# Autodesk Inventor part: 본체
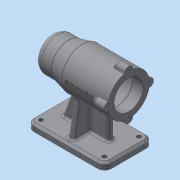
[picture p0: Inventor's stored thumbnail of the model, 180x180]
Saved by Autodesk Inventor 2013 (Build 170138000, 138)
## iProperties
Created: 2019-07
Part Number: 본체
Material: 일반
Document SubType Name: Modeling
Designer: dgall
Density: 1 g/cm^3
Author: dgall
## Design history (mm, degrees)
sketch "스케치1"
  geometry: L1 (0, 0)-(112, 0); L2 (112, 0)-(112, 70); L3 (112, 70)-(0, 70); L4 (0, 70)-(0, 0)
  constraints: 8 end point, 2 parallel, 1 horizontal, 1 perpendicular
  dimensions: "d5" = 70 distance of L1.end L2.end; "d6" = 112 distance of L2.end L3.end
extrude "돌출1" new body sketch "스케치1" distance "d7" = 10; taper "d8" = 0 deg
fillet "모깎기1" dims "d9" = 10
chamfer "모따기1" distance "d10" = 3; stored, may be unused: second distance "d11" = 2, angle "d12" = 45 deg
hole "구멍1" diameter "d15" = 6; stored, may be unused: countersink angle "d19" = 90 deg, drill point angle "d21" = 118 deg; dims "d13" = 10, "d14" = 10, "d16" = 6, "d17" = 4, "d18" = 2, "d20" = 27.5
hole "구멍2" diameter "d24" = 6; stored, may be unused: countersink angle "d28" = 90 deg, drill point angle "d30" = 118 deg; dims "d22" = 10, "d23" = 10, "d25" = 6, "d26" = 4, "d27" = 2, "d29" = 27.5
hole "구멍3" diameter "d33" = 6; stored, may be unused: countersink angle "d37" = 90 deg, drill point angle "d39" = 118 deg; dims "d31" = 10, "d32" = 10, "d34" = 6, "d35" = 4, "d36" = 2, "d38" = 27.5
hole "구멍4" diameter "d42" = 6; stored, may be unused: countersink angle "d46" = 90 deg, drill point angle "d48" = 118 deg; dims "d40" = 10, "d41" = 10, "d43" = 6, "d44" = 4, "d45" = 2, "d47" = 27.5
node "작업 평면2"
sketch "스케치2"
  geometry: L1 (0, 0)-(-112, 0); L2 (-56, 0)-(-56, 80); L3 (-56, 80)-(-112, 80); L4 (-56, 80)-(0, 80); L5 (-112, 80)-(-112, 101); L6 (-112, 101)-(-97, 101); L7 (-97, 101)-(-97, 101); L8 (-94, 104)-(-46, 104); L9 (-43, 101)-(-43, 101); L10 (-43, 101)-(-31.3, 101); L11 (-31, 100.7)-(-31, 97.5); L12 (-31, 97.5)-(-13.3, 97.5); L13 (-13, 97.2)-(-13, 96); L14 (-13, 96)-(-9.3, 96); L15 (-9, 95.7)-(-9, 90.5); L16 (-9, 90.5)-(-9, 90.5); L17 (-6, 87.5)-(-6, 80); L18 (0, 80)-(0, 95); L19 (-10, 105)-(-25, 105); L20 (-25, 105)-(-45, 110); L21 (-45, 110)-(-112, 110); L22 (-112, 110)-(-112, 101); A1 r 0.3 centre (-9.3, 95.7) between (-9, 95.7) and (-9.3, 96); A2 r 0.3 centre (-13.3, 97.2) between (-13, 97.2) and (-13.3, 97.5); A3 r 0.3 centre (-31.3, 100.7) between (-31, 100.7) and (-31.3, 101); A4 r 3 centre (-46, 101) between (-43, 101) and (-46, 104); A5 r 3 centre (-94, 101) between (-94, 104) and (-97, 101); A6 r 3 centre (-9, 87.5) between (-6, 87.5) and (-9, 90.5); A7 r 10 centre (-10, 95) between (0, 95) and (-10, 105); 7 further points
  constraints: 44 end point, 17 perpendicular, 15 point on line, 14 point on circle, 14 tangent, 7 centre point, 3 equal radius, 2 parallel, 1 collinear, 1 horizontal, 1 midpoint
  dimensions: "d50" = 112 distance of L1.start L1.end; "d54" = 80 distance of L2.start L2.end; "d55" = 21 distance of L3.end L5.end; "d57" = 48 diameter of point (-97, 104) L3; "d58" = 54 distance of point (-97, 104) point (-43, 104); "d59" = 56 distance from line of L2.end L5; "d60" = 42 diameter of L9.end L4; "d61" = 12 distance of L9.end point (-31, 101); "d62" = 35 diameter of L11.end L4; "d63" = 18 distance of L11.end point (-13, 97.5); "d64" = 32 diameter of L13.end L4; "d65" = 4 distance of L13.end point (-9, 96); "d66" = 21 diameter of L15.end L4; "d67" = 3 distance of L15.end point (-6, 90.5); "d68" = 0.3 radius of A1; "d69" = 3 radius of A4; "d70" = 50 diameter of point (0, 105) L4; "d71" = 25 distance of point (0, 105) L19.end; "d72" = 60 diameter of L20.end L4; "d73" = 45 horizontal distance of point (0, 105) L20.end; "d74" = 15 distance of L5.end L6.end; "d75" = 112 horizontal distance of point (0, 105) L21.end; "d76" = 3 radius of A6; "d77" = 10 radius of A7
revolve "회전1" sketch "스케치2" stored, may be unused: angle "d78" = 90 deg
sketch "스케치3"
  geometry: L1 (-30, 0)-(30, 0); L2 (0, -30)-(0, 30); A1 r 6 centre (-30, 0) between (-29.4, 5.97) and (-29.4, -5.97); A2 r 6 centre (0, 30) between (5.97, 29.4) and (-5.97, 29.4); A3 r 6 centre (0, -30) between (-5.97, -29.4) and (5.97, -29.4); A4 r 6 centre (30, 0) between (29.4, -5.97) and (29.4, 5.97); 2 further points
  constraints: 8 point on circle, 4 centre point, 4 coincident, 4 end point, 2 equal radius, 1 horizontal, 1 perpendicular, 13 other
  dimensions: "d79" = 60 distance of L1.start L1.end; "d80" = 60 distance of L2.start L2.end; "d81" = 12 diameter of A1; "d82" = 12 diameter of A3
extrude "돌출2" join sketch "스케치3" distance "d83" = 16; taper "d84" = 0 deg
hole "구멍5" sketch "스케치3" diameter "d85" = 3.242; stored, may be unused: countersink angle "d89" = 90 deg, drill point angle "d91" = 118 deg; dims "d86" = 8, "d87" = 4, "d88" = 2, "d90" = 11
fillet "모깎기2" dims "d92" = 3
fillet "모깎기3" dims "d93" = 1
node "작업 평면3"
sketch "스케치4"
  geometry: L1 (0, 0)-(0, 70); L2 (0, 35)-(20, 35); L3 (0, 0)-(112, 0); L4 (112, 0)-(112, 70); L5 (112, 35)-(87, 35); L6 (87, 39)-(87, 31); L7 (20, 39)-(20, 31); L8 (56, 0)-(56, 7); L9 (0, 70)-(112, 70); L10 (56, 70)-(56, 63); L11 (52, 7)-(60, 7); L12 (52, 63)-(60, 63); L13 (20, 39)-(52, 39); L14 (60, 39)-(87, 39); L15 (60, 63)-(60, 39); L16 (60, 31)-(60, 7); L17 (52, 63)-(52, 39); L18 (52, 31)-(52, 7); L19 (87, 31)-(60, 31); L20 (52, 31)-(20, 31); 4 further points
  constraints: 40 end point, 10 perpendicular, 9 parallel, 8 midpoint, 1 horizontal alignment, 1 vertical, 1 vertical alignment
  dimensions: "d95" = 70 distance of L1.start L1.end; "d100" = 112 distance of L1.start L3.end; "d101" = 70 distance of L3.end L4.end; "d102" = 25 distance of L5.start L5.end; "d103" = 8 distance of L7.start L7.end; "d104" = 67 distance of L7.start L6.start; "d105" = 92 horizontal distance of L5.start L7.start; "d106" = 4 distance of L5.end L6.start; "d107" = 4 distance of L2.end L7.end; "d109" = 8 distance of L11.end L11.start; "d114" = 7 distance from line of L9 L12.end; "d115" = 7 distance from line of L3 L11.end; "d116" = 24 distance of L12.end L14.start; "d117" = 32 distance of L18.start L7.end; "d118" = 27 distance of L6.end L16.start; "d119" = 24 distance of L18.start L11.start; "d120" = 24 distance of L16.start L11.end; "d121" = 8 distance of L12.start L12.end; "d122" = 63 distance from line of L3 L10.end; "d123" = 41.7732 distance of L5.end L8.end
extrude "돌출3" join sketch "스케치4" stored distance "d124" = 16; taper "d125" = 0 deg
feature "면 기울기1" dims angle "d126" = 20 deg
feature "면 기울기2" dims angle "d127" = 10 deg
fillet "모깎기4" dims "d128" = 3
fillet "모깎기5" dims "d129" = 1
fillet "모깎기6" dims "d130" = 3
node "작업 평면4"
sketch "스케치5"
  geometry: L1 (112, 110.171)-(112, 116) reference; L2 (112, 74.002)-(112, 85.998) reference; 3 further points
  constraints: 1 horizontal alignment, 1 midpoint, 1 other
  dimensions: "d132" = 42 distance from line of L1 point (70, 80)
feature "엠보싱1" sketch "스케치5" dims "d5" = 70, "d6" = 112, "d133" = 0.5, "d134" = 0
node "솔리드1"
other parameters: "d49" = 35, "d131" = 5
